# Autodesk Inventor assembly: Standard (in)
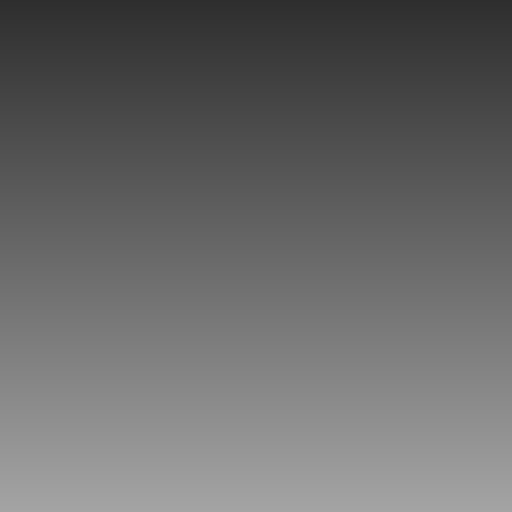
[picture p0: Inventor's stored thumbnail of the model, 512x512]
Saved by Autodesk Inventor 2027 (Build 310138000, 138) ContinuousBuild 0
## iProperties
Shininess: 64.0
Length Units: 11272
Angle Units: 11279
Time Units: 11290
Mass Units: 11286
Length Display Precision: 3
Angle Display Precision: 2
Compacted: True
Part Number: Standard (in)
Document SubType Name: Assembly
Created: 2002-07
Designer: invbi
Density: 0.0
Volumn: 0.0
Area: 0.0
PropertySet Name: Model Information
Control State: 0
Master: False
Checked Out: False
Author: invbi
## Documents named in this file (1)
- D:\AUTOBUILD\inventor\Application\App\Templates\en-US\English\Standard (in).iam
